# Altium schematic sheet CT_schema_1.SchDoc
size 572 x 514 mm
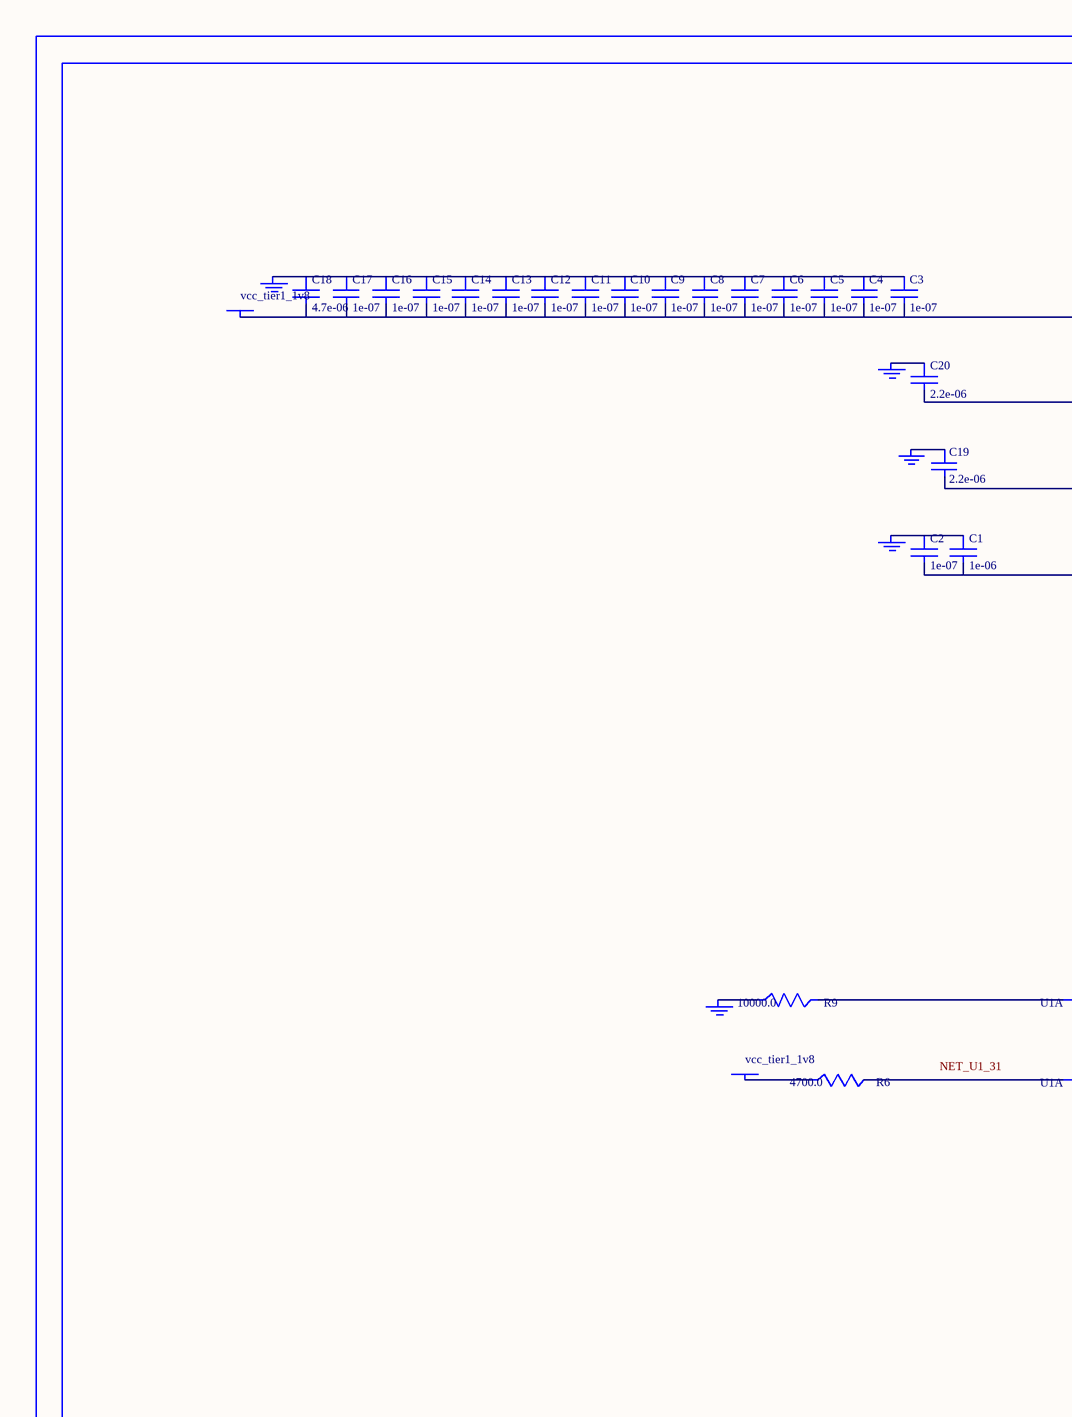
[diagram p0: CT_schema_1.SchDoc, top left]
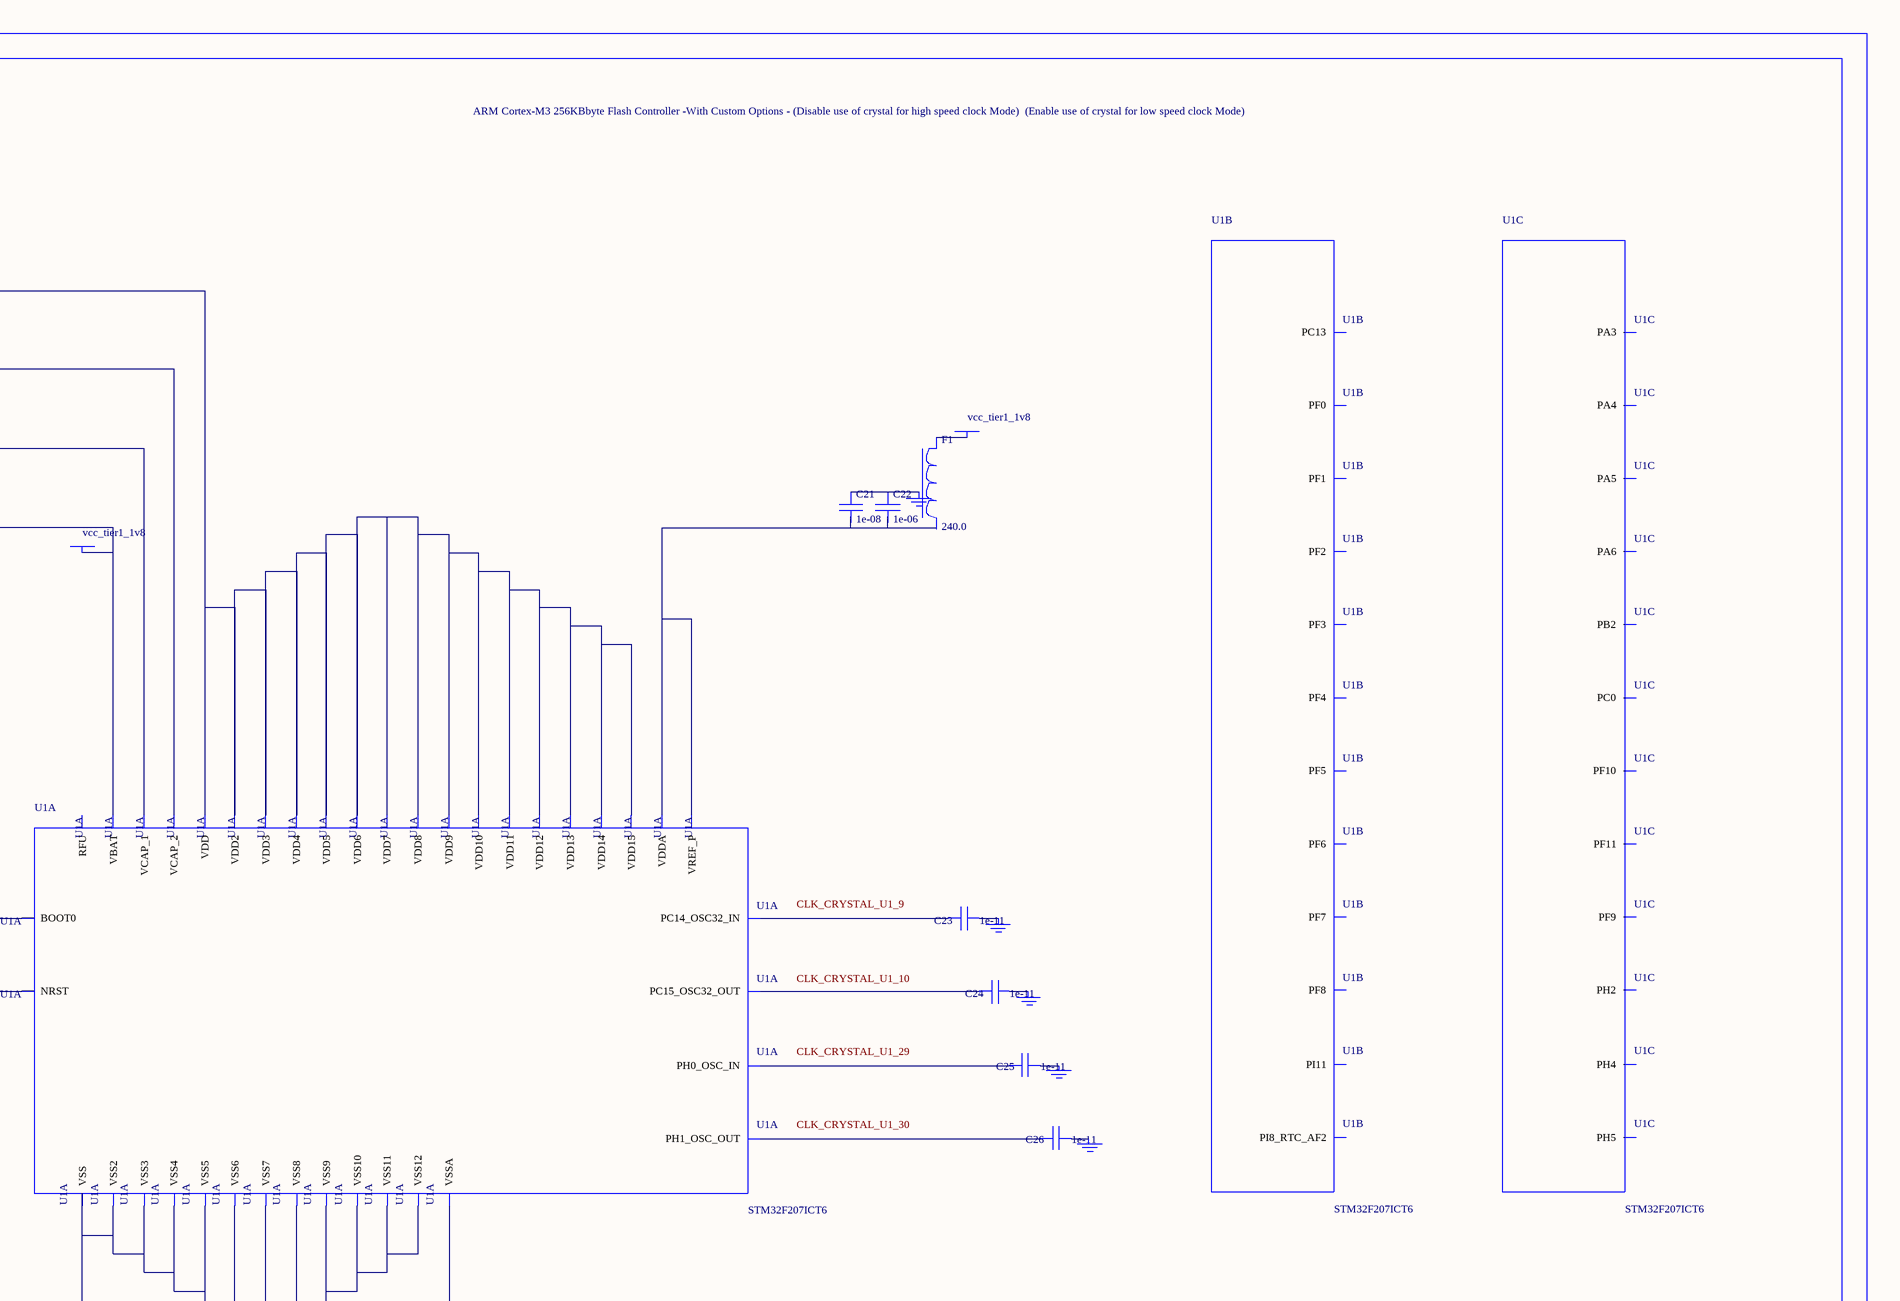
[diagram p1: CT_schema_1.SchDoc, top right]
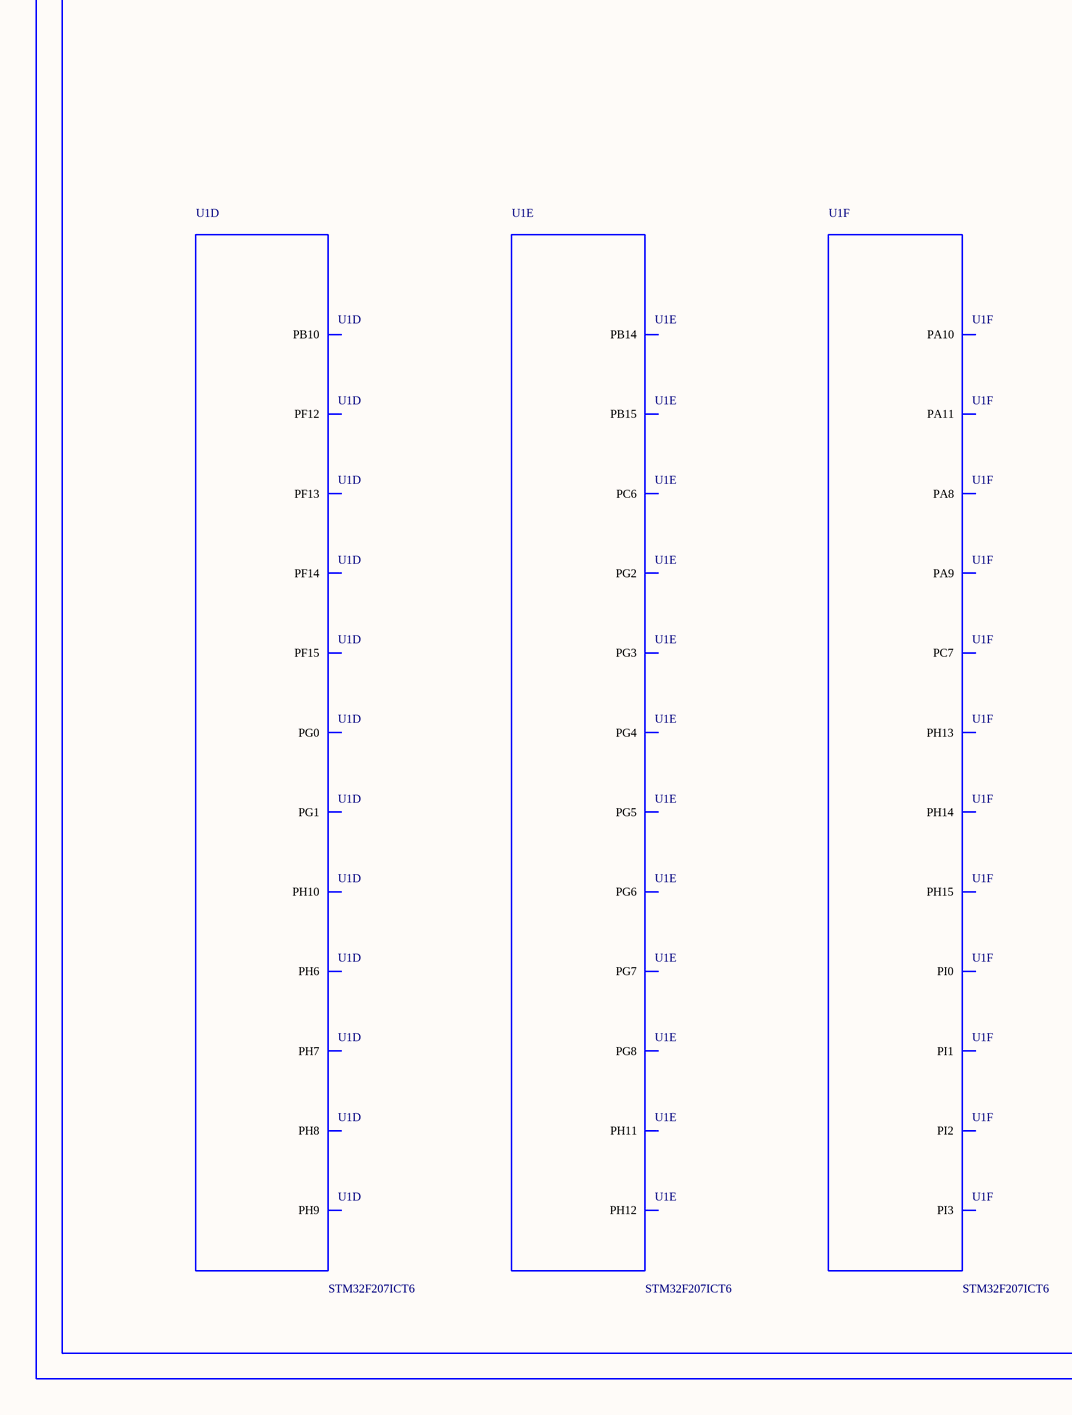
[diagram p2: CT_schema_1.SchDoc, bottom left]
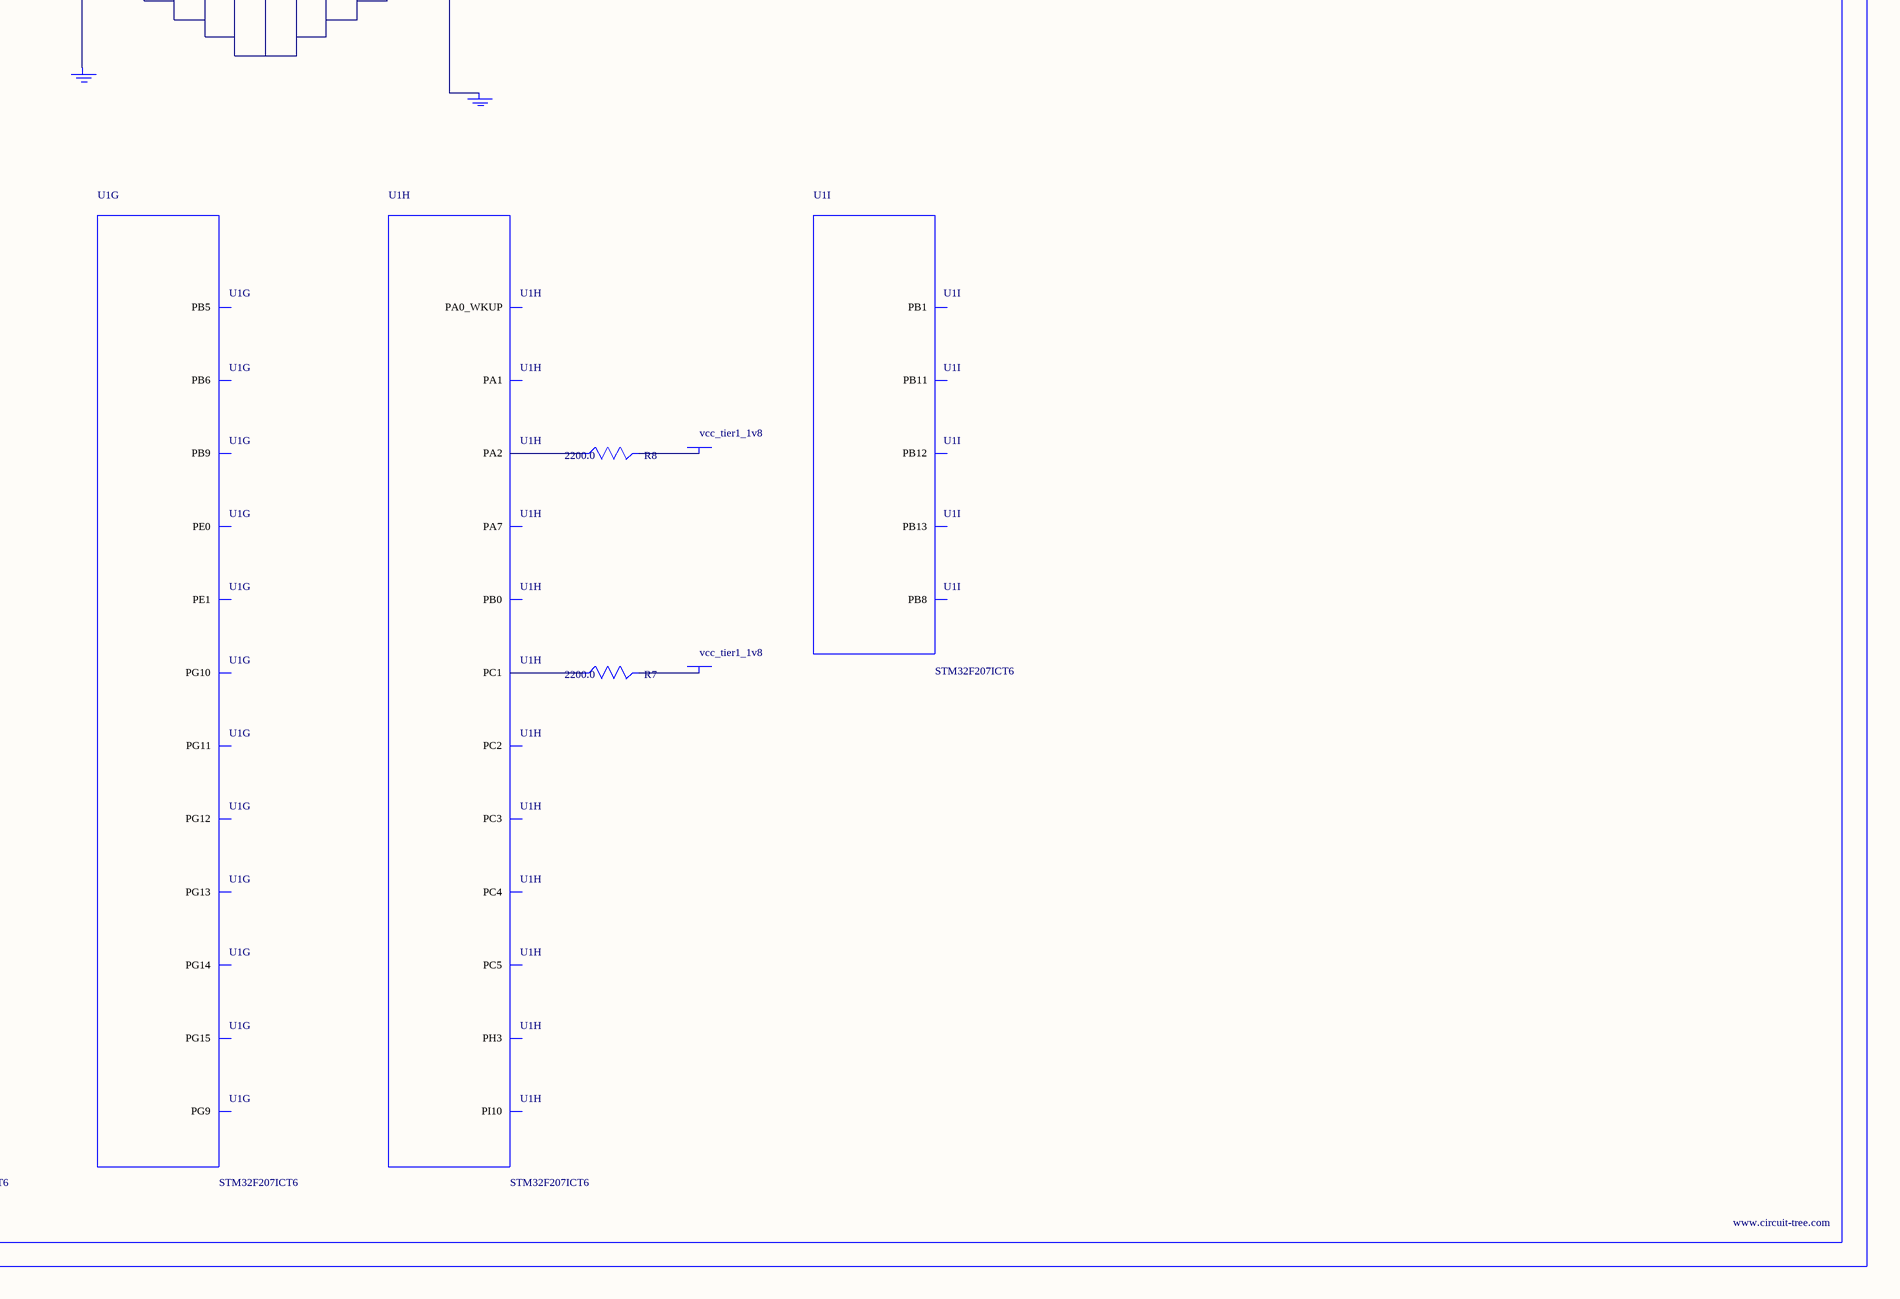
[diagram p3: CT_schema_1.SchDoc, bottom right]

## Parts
BORDER0  (no value)
C1  1e-06  [C0603]
C2  1e-07  [C0603]
C3  1e-07  [C0603]
C4  1e-07  [C0603]
C5  1e-07  [C0603]
C6  1e-07  [C0603]
C7  1e-07  [C0603]
C8  1e-07  [C0603]
C9  1e-07  [C0603]
C10  1e-07  [C0603]
C11  1e-07  [C0603]
C12  1e-07  [C0603]
C13  1e-07  [C0603]
C14  1e-07  [C0603]
C15  1e-07  [C0603]
C16  1e-07  [C0603]
C17  1e-07  [C0603]
C18  4.7e-06  [C0603]
C19  2.2e-06  [C0603]
C20  2.2e-06  [C0603]
C21  1e-08  [C0603]
C22  1e-06  [C0603]
C23  1e-11  [C0402]
C24  1e-11  [C0402]
C25  1e-11  [C0402]
C26  1e-11  [C0402]
F1  240.0  [L0603]
GND_INSTANCE_0_0  (no value)
GND_INSTANCE_0_1  (no value)
GND_INSTANCE_0_2  (no value)
GND_INSTANCE_0_3  (no value)
GND_INSTANCE_0_4  (no value)
GND_INSTANCE_0_5  (no value)
GND_INSTANCE_0_6  (no value)
GND_INSTANCE_0_7  (no value)
GND_INSTANCE_0_8  (no value)
GND_INSTANCE_0_9  (no value)
GND_INSTANCE_0_10  (no value)
GND_INSTANCE_0_11  (no value)
POWER_INSTANCE_0_0  vcc_tier1_1v8
POWER_INSTANCE_0_1  vcc_tier1_1v8
POWER_INSTANCE_0_2  vcc_tier1_1v8
POWER_INSTANCE_0_3  vcc_tier1_1v8
POWER_INSTANCE_0_4  vcc_tier1_1v8
POWER_INSTANCE_0_5  vcc_tier1_1v8
R6  4700.0  [R0603]
R7  2200.0  [R0603]
R8  2200.0  [R0603]
R9  10000.0  [R0603]
U1  STM32F207ICT6  [LQFP176]  (parts A,B,C,D,E,F,G,H,I of 14)

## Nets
NetC1_1: C1.1 C2.1 GND_INSTANCE_0_0.0(GND)
NetC1_2: C1.2 C2.2 POWER_INSTANCE_0_0.0(PWR) U1.6(VBAT)
NetC3_1: C3.1 C4.1 C5.1 C6.1 C7.1 C8.1 C9.1 C10.1 C11.1 C12.1 C13.1 C14.1 C15.1 C16.1 C17.1 C18.1 GND_INSTANCE_0_3.0(GND)
NetC3_2: C3.2 C4.2 C5.2 C6.2 C7.2 C8.2 C9.2 C10.2 C11.2 C12.2 C13.2 C14.2 C15.2 C16.2 C17.2 C18.2 POWER_INSTANCE_0_1.0(PWR) U1.15(VDD) U1.23(VDD2) U1.36(VDD3) U1.49(VDD4) U1.62(VDD5) U1.72(VDD6) U1.82(VDD7) U1.91(VDD8) U1.103(VDD9) U1.114(VDD10) U1.127(VDD11) U1.136(VDD12) U1.149(VDD13) U1.159(VDD14) U1.172(VDD15)
NetC19_1: C19.1 GND_INSTANCE_0_8.0(GND)
NetC19_2: C19.2 U1.81(VCAP_1)
NetC20_1: C20.1 GND_INSTANCE_0_9.0(GND)
NetC20_2: C20.2 U1.125(VCAP_2)
NetC21_1: C21.1 C22.1 GND_INSTANCE_0_7.0(GND)
NetC21_2: C21.2 C22.2 U1.38(VREF_P) U1.39(VDDA)
NetC23_1: C23.1 GND_INSTANCE_0_1.0(GND)
NetC23_2: C23.2 U1.9(PC14_OSC32_IN)
NetC24_1: C24.1 GND_INSTANCE_0_2.0(GND)
NetC24_2: C24.2 U1.10(PC15_OSC32_OUT)
NetC25_1: C25.1 GND_INSTANCE_0_4.0(GND)
NetC25_2: C25.2 U1.29(PH0_OSC_IN)
NetC26_1: C26.1 GND_INSTANCE_0_5.0(GND)
NetC26_2: C26.2 U1.30(PH1_OSC_OUT)
NetF1_1: F1.1 POWER_INSTANCE_0_2.0(PWR)
NetGND_INSTANCE_0_6_0: GND_INSTANCE_0_6.0(GND) U1.37(VSSA)
NetGND_INSTANCE_0_10_0: GND_INSTANCE_0_10.0(GND) R9.1
NetGND_INSTANCE_0_11_0: GND_INSTANCE_0_11.0(GND) U1.14(VSS) U1.22(VSS2) U1.48(VSS3) U1.61(VSS4) U1.71(VSS5) U1.90(VSS6) U1.102(VSS7) U1.113(VSS8) U1.126(VSS9) U1.135(VSS10) U1.148(VSS11) U1.158(VSS12)
NetPOWER_INSTANCE_0_3_0: POWER_INSTANCE_0_3.0(PWR) R6.1
NetPOWER_INSTANCE_0_4_0: POWER_INSTANCE_0_4.0(PWR) R7.2
NetPOWER_INSTANCE_0_5_0: POWER_INSTANCE_0_5.0(PWR) R8.2
NetR6_2: R6.2 U1.31(NRST)
NetR7_1: R7.1 U1.33(PC1)
NetR8_1: R8.1 U1.42(PA2)
NetR9_2: R9.2 U1.166(BOOT0)

Not connected (* = marked no-connect by the designer): F1 2; U1 7(PI8_RTC_AF2) 8(PC13) 12(PI10) 13(PI11) 16(PF0) 17(PF1) 18(PF2) 19(PF3) 20(PF4) 21(PF5) 24(PF6) 25(PF7) 26(PF8) 27(PF9) 28(PF10) 32(PC0) 34(PC2) 35(PC3) 40(PA0_WKUP) 41(PA1) 43(PH2) 44(PH3) 45(PH4) 46(PH5) 47(PA3) 50(PA4) 51(PA5) 52(PA6) 53(PA7) 54(PC4) 55(PC5) 56(PB0) 57(PB1) 58(PB2) 59(PF11) 60(PF12) 63(PF13) 64(PF14) 65(PF15) 66(PG0) 67(PG1) 79(PB10) 80(PB11) 83(PH6) 84(PH7) 85(PH8) 86(PH9) 87(PH10) 88(PH11) 89(PH12) 92(PB12) 93(PB13) 94(PB14) 95(PB15) 106(PG2) 107(PG3) 108(PG4) 109(PG5) 110(PG6) 111(PG7) 112(PG8) 115(PC6) 116(PC7) 119(PA8) 120(PA9) 121(PA10) 122(PA11) 128(PH13) 129(PH14) 130(PH15) 131(PI0) 132(PI1) 133(PI2) 134(PI3) 152(PG9) 153(PG10) 154(PG11) 155(PG12) 156(PG13) 157(PG14) 160(PG15) 163(PB5) 164(PB6) 167(PB8) 168(PB9) 169(PE0) 170(PE1) 171(RFU)

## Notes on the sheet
- Labels drawn without touching a wire or pin: CLK_CRYSTAL_U1_9, CLK_CRYSTAL_U1_10, CLK_CRYSTAL_U1_29, CLK_CRYSTAL_U1_30, NET_U1_31

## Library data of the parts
BORDER0 = BORDER_PAGE0
C1 C22 = C0603C105K3RACTU
C2-C17 = 06035C104K4Z2A
C18 = GRM188R6YA475KE15D
C19 C20 = C0603C225K8RACTU
C21 = 06035C103K4Z2A
C23-C26 = C0402C100K3GACTU
F1 = Z0603C241ASMST
GND_INSTANCE_0_0-GND_INSTANCE_0_11 = GND
POWER_INSTANCE_0_0-POWER_INSTANCE_0_5 = PWR
R6 = RC0603JR-074K7L
R7 R8 = RC0603JR-072K2L
R9 = RC0603JR-0710KL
